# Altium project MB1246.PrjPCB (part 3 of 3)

## Sheet LCD Connectors.SchDoc: LCD Connectors
size A4; DocumentNumber: MB1246; Revision: B.2; SheetNumber: 6; SheetTotal: 17; Project: STM32H7x3I-EVAL
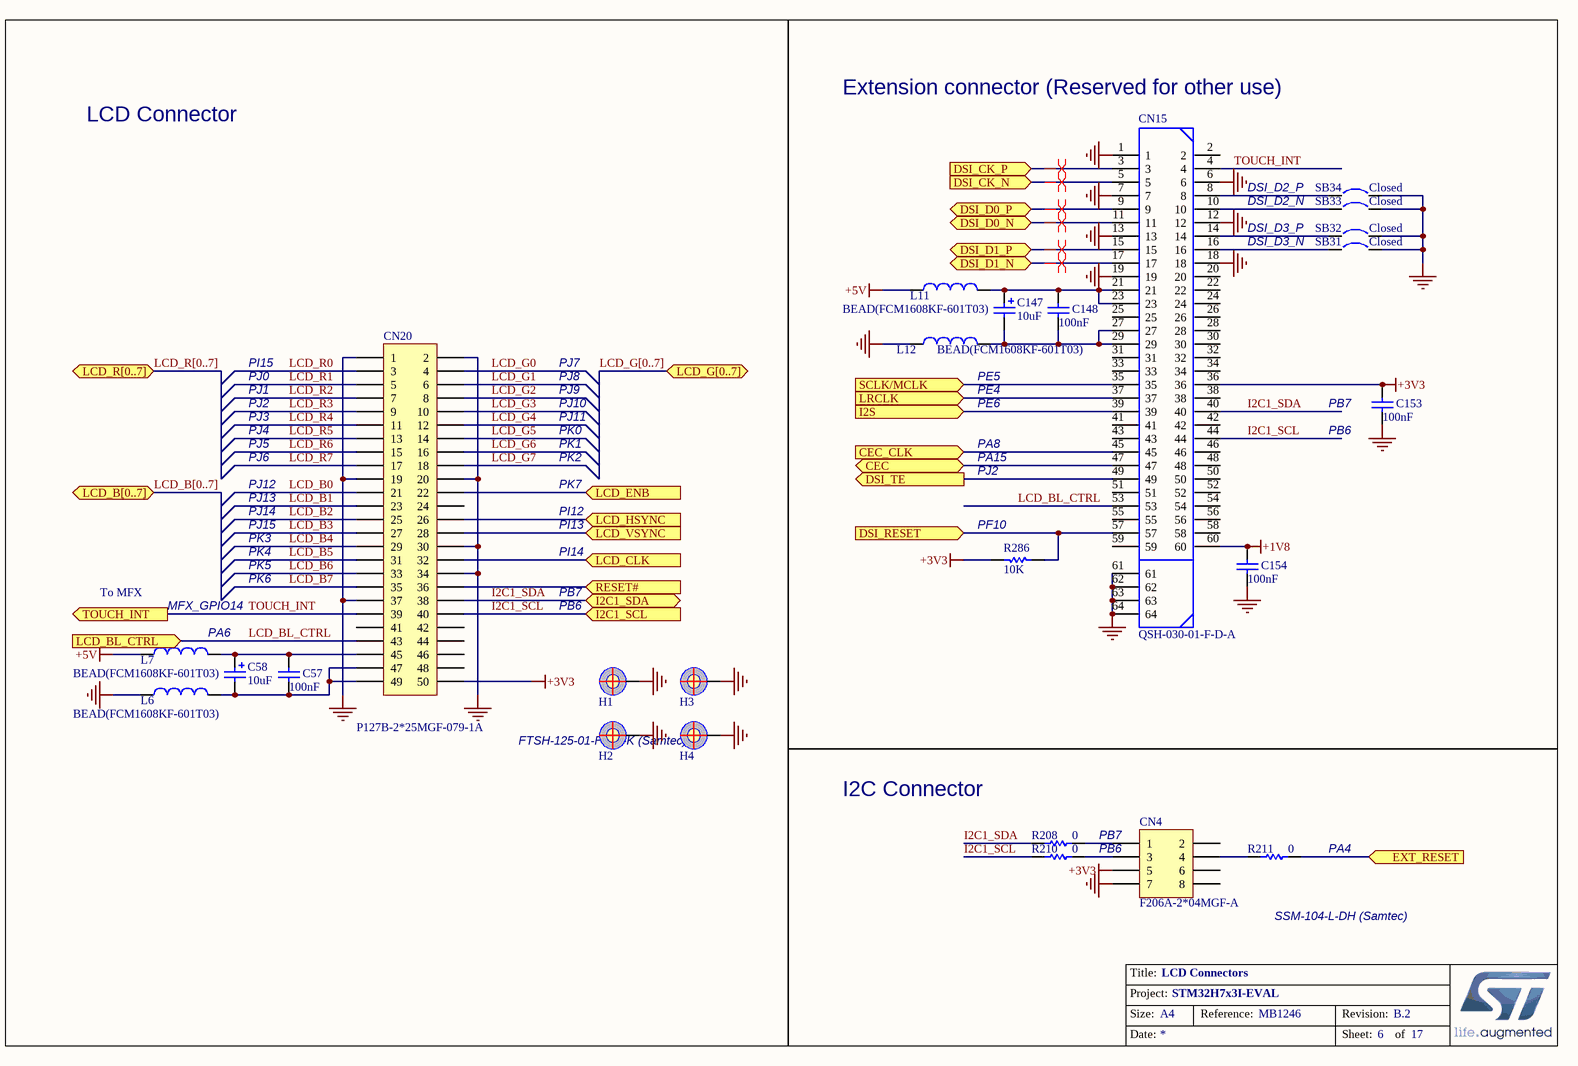
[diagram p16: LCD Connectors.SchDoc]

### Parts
C57  100nF  [0603C]
C58  10uF  [TAN-A]
C147  10uF  [TAN-A]
C148  100nF  [0603C]
C153  100nF  [0603C]
C154  100nF  [0603C]
CN4  F206A-2*04MGF-A  [SSM-104-L-DH]
CN15  QSH-030-01-F-D-A  [QSH-030-01-F-D-A]
CN20  P127B-2*25MGF-079-1A  [FTSH-125-01-F-DV]
H1  POSITION HOLE  [HOLE_C9D4R5]  (value not drawn)
H2  POSITION HOLE  [HOLE_C9D4R5]  (value not drawn)
H3  POSITION HOLE  [HOLE_C9D4R5]  (value not drawn)
H4  POSITION HOLE  [HOLE_C9D4R5]  (value not drawn)
L6  BEAD(FCM1608KF-601T03)  [0603L]
L7  BEAD(FCM1608KF-601T03)  [0603L]
L11  BEAD(FCM1608KF-601T03)  [0603L]
L12  BEAD(FCM1608KF-601T03)  [0603L]
R208  0  [0603R]
R210  0  [0603R]
R211  0  [0603R]
R286  10K  [0603R]
SB31  Closed  [SB_0603]
SB32  Closed  [SB_0603]
SB33  Closed  [SB_0603]
SB34  Closed  [SB_0603]

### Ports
CEC (bidir), CEC_CLK (in), DSI_CK_N (in), DSI_CK_P (in), DSI_D0_N (bidir), DSI_D0_P (bidir), DSI_D1_N (bidir), DSI_D1_P (bidir), DSI_RESET (in), DSI_TE (out), EXT_RESET (in), I2C1_SCL (in), I2C1_SDA (bidir), I2S (in), LCD_B[0..7] (bidir), LCD_BL_CTRL (in), LCD_CLK (in), LCD_ENB (in), LCD_G[0..7] (bidir), LCD_HSYNC (in), LCD_R[0..7] (bidir), LCD_VSYNC (in), LRCLK (in), RESET# (in), SCLK/MCLK (in), TOUCH_INT (out)

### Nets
+1V8: C154.1 CN15.60
+3V3: C153.1 CN4.5 CN15.36 CN20.50 R286.2
+5V: L7.1 L11.1
GND: C153.2 C154.2 CN4.7 CN15.1 CN15.6 CN15.7 CN15.12 CN15.13 CN15.18 CN15.19 CN15.61 CN15.62 CN15.63 CN15.64 CN20.1 CN20.2 CN20.19 CN20.20 CN20.30 CN20.34 CN20.37 H1.1 H2.1 H3.1 H4.1 L6.1 L12.1 SB31.2 SB32.2 SB33.2 SB34.2
I2C1_SCL: CN15.44 CN20.40 R210.1 ; port I2C1_SCL
I2C1_SDA: CN15.40 CN20.38 R208.1 ; port I2C1_SDA
LCD_B0: CN20.21
LCD_B1: CN20.23
LCD_B2: CN20.25
LCD_B3: CN20.27
LCD_B4: CN20.29
LCD_B5: CN20.31
LCD_B6: CN20.33
LCD_B7: CN20.35
LCD_BL_CTRL: CN15.53 CN20.43 ; port LCD_BL_CTRL
LCD_G0: CN20.4
LCD_G1: CN20.6
LCD_G2: CN20.8
LCD_G3: CN20.10
LCD_G4: CN20.12
LCD_G5: CN20.14
LCD_G6: CN20.16
LCD_G7: CN20.18
LCD_R0: CN20.3
LCD_R1: CN20.5
LCD_R2: CN20.7
LCD_R3: CN15.49 CN20.9 ; port DSI_TE
LCD_R4: CN20.11
LCD_R5: CN20.13
LCD_R6: CN20.15
LCD_R7: CN20.17
PA4: R211.2 ; port EXT_RESET
PA8: CN15.45 ; port CEC_CLK
PA15: CN15.47 ; port CEC
PF10: CN15.57 R286.1 ; port DSI_RESET
PI12: CN20.26 ; port LCD_HSYNC
PI13: CN20.28 ; port LCD_VSYNC
PI14: CN20.32 ; port LCD_CLK
PK7: CN20.22 ; port LCD_ENB
RESET#: CN20.36 ; port RESET#
TOUCH_INT: CN15.4 CN20.39 ; port TOUCH_INT
NetC57_1: C57.1 C58.1 CN20.45 L7.2
NetC57_2: C57.2 C58.2 CN20.47 CN20.49 L6.2
NetC147_1: C147.1 C148.1 CN15.21 CN15.23 L11.2
NetC147_2: C147.2 C148.2 CN15.27 CN15.29 L12.2
NetCN4_1: CN4.1 R208.2
NetCN4_3: CN4.3 R210.2
NetCN4_4: CN4.4 R211.1
NetCN15_3: CN15.3 ; port DSI_CK_P
NetCN15_5: CN15.5 ; port DSI_CK_N
NetCN15_8: CN15.8 SB34.1
NetCN15_9: CN15.9 ; port DSI_D0_P
NetCN15_10: CN15.10 SB33.1
NetCN15_11: CN15.11 ; port DSI_D0_N
NetCN15_14: CN15.14 SB32.1
NetCN15_15: CN15.15 ; port DSI_D1_P
NetCN15_16: CN15.16 SB31.1
NetCN15_17: CN15.17 ; port DSI_D1_N
NetCN15_35: CN15.35 ; port SCLK/MCLK
NetCN15_37: CN15.37 ; port LRCLK
NetCN15_39: CN15.39 ; port I2S

Not connected (* = marked no-connect by the designer): CN4 2 6 8; CN15 2 20 22 24 25 26 28 30 31 32 33 34 38 41 42 43 46 48 50 51 52 54 55 56 58 59; CN20 24 41 42 44 46 48

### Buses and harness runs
bus LCD_B[0..7] = port LCD_B[0..7]
bus LCD_G[0..7] = port LCD_G[0..7]
bus LCD_R[0..7] = port LCD_R[0..7]

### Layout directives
differential pair: NetCN15_3, NetCN15_5, NetCN15_9, NetCN15_11, NetCN15_15, NetCN15_17

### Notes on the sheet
- LCD Connector
- Extension connector (Reserved for other use)
- DSI_D2_P
- DSI_D2_N
- DSI_D3_P
- DSI_D3_N
- PI15
- PJ0
- PJ1
- PJ7
- PJ8
- PJ9
- (near L12) PE5
- (near L12) PE4
- PJ2
- PJ3
- PJ4
- PJ5
- PJ6
- PJ10
- PJ11
- PK0
- PK1
- PK2
- PE6
- PA15
- PA8
- (near C153) PB7
- (near C153) PB6
- PJ12
- PJ13
- PJ14
- PJ15
- PK7
- PI12
- PI13
- (near R286) PF10
- To MFX
- PK3
- PK4
- PK5
- PK6
- PI14
- PB7
- MFX_GPIO14
- (near L7) PA6
- PB6
- FTSH-125-01-F-DV-K (Samtec)
- I2C Connector
- (near R211) PA4
- (near CN4) SSM-104-L-DH (Samtec)

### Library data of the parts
C57 C148 C153 C154 = Cap: Capacitor; Value: 10nF
C58 C147 = Cap Pol1: Polarized Capacitor (Radial)
CN4 = SSM-104-L-DH: Header, 5-Pin, Dual row
CN15 = QSH-030-01-F-D-A: HIGH SPEED SOCKET STRIP, .5mm PITCH, 60 PINS; MANUFACTURER: SAMTEC; PCB DECAL: QSH-030-01-X-D-A
CN20 = Header 25X2: Header, 26-Pin, Dual row
L6 L7 L11 L12 = Inductor: Value: 100uH
R208 R210 R211 R286 = Res1: Resistor; Value: 1K
SB31-SB34 = Circuit Breaker_close: Circuit Breaker

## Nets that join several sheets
+1V8: Audio (6 pins), Power (SB36.2 SB37.2 TP12.1), USB_OTG (C141.1 R130.1 U13.28 U13.30), LCD Connectors (C154.1 CN15.60)
+2V9_SD: Power (5 pins), SD card (CN13.4 SB26.1)
+3V3: MB1246 (R209.1 R212.1), Audio (11 pins), ExtensionConnector (CN6.48 CN7.48 CN12.40), FDCAN&QSPI (9 pins), Memory (45 pins), MFX (13 pins), Power (9 pins), ST_LINK_V2-1 (R164.1), USB_OTG_FS (R144.1 R165.2 R290.2), SD card (7 pins), JTAG&Trace (8 pins), Ethernet (8 pins), RS232 (C104.1 U4.22 U4.26), Peripherals (15 pins), MCU (R247.1 SW1.1), USB_OTG (11 pins), LCD Connectors (5 pins)
+5V: ExtensionConnector (CN6.60 CN7.60), FDCAN&QSPI (C100.1 U2.3), Power (13 pins), ST_LINK_V2-1 (D16.1), USB_OTG_FS (U18.5), USB_OTG (C39.1 U13.21 U14.5), LCD Connectors (L7.1 L11.1)
D5V: ExtensionConnector (CN6.49 CN7.49), Power (JP10.7), ST_LINK_V2-1 (D7.1)
E5V: Power (C36.1 JP10.9 L3.3), ST_LINK_V2-1 (D8.1)
GND: Audio (43 pins), ExtensionConnector (20 pins), FDCAN&QSPI (14 pins), Memory (40 pins), MFX (16 pins), Power (106 pins), ST_LINK_V2-1 (42 pins), USB_OTG_FS (13 pins), SD card (5 pins), JTAG&Trace (24 pins), Ethernet (22 pins), RS232 (8 pins), Peripherals (16 pins), MCU (16 pins), USB_OTG (40 pins), LCD Connectors (31 pins)
U5V_ST_LINK: Power (JP10.11), ST_LINK_V2-1 (C49.2 SB35.2 U19.6 U19.7)
VBUS_FS1: Power (JP10.3), ST_LINK_V2-1 (D5.1), USB_OTG_FS (5 pins), MCU (R255.1)
VBUS_FS2: Power (JP10.5), ST_LINK_V2-1 (D6.1), MCU (R254.1), USB_OTG (CN16.1 D13.6 R135.1 SB28.1)
VBUS_HS: Power (JP10.1), ST_LINK_V2-1 (D4.1), USB_OTG (CN14.1 D11.A1 L5.2)
A0: ExtensionConnector (CN12.14), Memory (U12.E2 U15.G8 U16.A3), MCU (R224.1)
A1: ExtensionConnector (CN12.12), Memory (U12.D2 U15.G9 U16.A4), MCU (R226.1)
A2: ExtensionConnector (CN12.8), Memory (U12.C2 U15.F7 U16.A5), MCU (R222.1)
A3: ExtensionConnector (CN12.5), Memory (U12.A2 U15.F3 U16.B3), MCU (R223.1)
A4: ExtensionConnector (CN12.3), Memory (U12.B2 U15.G1 U16.B4), MCU (R221.1)
A5: ExtensionConnector (CN12.1), Memory (U12.D3 U15.G2 U16.C3), MCU (R219.1)
A6: ExtensionConnector (CN11.5), Memory (U12.C3 U15.G3 U16.C4), MCU (R250.1)
A7: ExtensionConnector (CN11.3), Memory (U12.A3 U15.H1 U16.D4), MCU (R251.1)
A8: ExtensionConnector (CN11.4), Memory (U12.B6 U15.H2 U16.H2), MCU (R53.1)
A9: ExtensionConnector (CN11.18), Memory (U12.A6 U15.J3 U16.H3), MCU (R279.1)
A10: ExtensionConnector (CN11.6), Memory (U12.C6 U15.G7 U16.H4), MCU (R50.1)
A11: ExtensionConnector (CN11.7), Memory (U12.D6 U15.H9 U16.H5), MCU (R51.1)
A12: ExtensionConnector (CN11.33), Memory (U12.B7 U16.G3), MCU (R270.1)
A13: ExtensionConnector (CN11.34), Memory (U12.A7 U16.G4), MCU (R260.1)
A14: ExtensionConnector (CN11.28), Memory (U12.C7 U15.J7 U16.F3), MCU (R261.1)
A15: ExtensionConnector (CN11.25), Memory (U12.D7 U15.H8 U16.F4), MCU (R272.1)
A16: ExtensionConnector (CN11.21), Memory (U12.E7 U16.E4), MCU (R275.2)
A17: ExtensionConnector (CN11.23), Memory (U12.B3 U16.D3), MCU (R274.1)
A18: ExtensionConnector (CN11.31), Memory (U12.C4 U16.H1), MCU (R271.1)
A19: ExtensionConnector (CN12.13), Memory (U12.D5 U16.G2), MCU (R236.1 R238.1)
A20: ExtensionConnector (CN12.11), Memory (U12.D4 U16.H6), MCU (R231.1 R233.1)
A21: ExtensionConnector (CN12.4), Memory (U12.C5), MCU (R217.1 R218.1)
A22: ExtensionConnector (CN12.7), Memory (U12.B8), MCU (R227.1 R230.1)
A23: ExtensionConnector (CN12.16), Memory (U12.C8), MCU (R234.1 R241.1)
BK2_IO0: ExtensionConnector (CN6.17), FDCAN&QSPI (R52.1 R253.1), MCU (R228.2)
BK2_IO1: ExtensionConnector (CN6.15), FDCAN&QSPI (R28.2 R229.2), MCU (R235.2)
BK2_IO2: ExtensionConnector (CN6.32), FDCAN&QSPI (R33.1 R237.1), MCU (R244.2)
BK2_IO3: ExtensionConnector (CN6.13), FDCAN&QSPI (R27.2 R225.2), MCU (R29.2)
D0: ExtensionConnector (CN11.39), Memory (U12.E3 U15.R8 U16.B6), MCU (R77.1)
D1: ExtensionConnector (CN11.38), Memory (U12.H3 U15.N7 U16.C5), MCU (R269.1)
D2: ExtensionConnector (CN12.31), Memory (U12.E4 U15.R9 U16.C6), MCU (R265.1)
D3: ExtensionConnector (CN12.32), Memory (U12.H4 U15.N8 U16.D5), MCU (R262.1)
D4: ExtensionConnector (CN11.11), Memory (U12.H5 U15.P9 U16.E5), MCU (R54.1)
D5: ExtensionConnector (CN11.14), Memory (U12.E5 U15.M8 U16.F5), MCU (R67.1)
D6: ExtensionConnector (CN11.12), Memory (U12.H6 U15.M7 U16.F6), MCU (R66.1)
D7: ExtensionConnector (CN11.13), Memory (U12.E6 U15.L8 U16.G6), MCU (R280.1)
D8: ExtensionConnector (CN11.16), Memory (U12.F3 U15.L2 U16.B1), MCU (R68.1)
D9: ExtensionConnector (CN11.15), Memory (U12.G3 U15.M3 U16.C1), MCU (R278.1)
D10: ExtensionConnector (CN11.19), Memory (U12.F4 U15.M2 U16.C2), MCU (R70.1)
D11: ExtensionConnector (CN11.20), Memory (U12.G4 U15.P1 U16.D2), MCU (R277.1)
D12: ExtensionConnector (CN11.17), Memory (U12.F5 U15.N2 U16.E2), MCU (R69.1)
D13: ExtensionConnector (CN11.35), Memory (U12.G6 U15.R1 U16.F2), MCU (R73.1)
D14: ExtensionConnector (CN11.37), Memory (U12.F6 U15.N3 U16.F1), MCU (R76.1)
D15: ExtensionConnector (CN11.36), Memory (U12.G7 U15.R2 U16.G1), MCU (R75.1)
D16: ExtensionConnector (CN11.22), Memory (U15.E8), MCU (R71.2)
D17: ExtensionConnector (CN11.26), Memory (U15.D7), MCU (R72.2)
D18: ExtensionConnector (CN11.24), Memory (U15.D8), MCU (R276.2)
D19: ExtensionConnector (CN11.27), Memory (U15.B9), MCU (R273.2)
D20: ExtensionConnector (CN11.32), Memory (U15.C8), MCU (R74.2)
D21: ExtensionConnector (CN12.39), Memory (U15.A9), MCU (R258.2)
D22: ExtensionConnector (CN12.38), Memory (U15.C7), MCU (R257.2)
D23: ExtensionConnector (CN12.36), Memory (U15.A8), MCU (R266.2)
D24: ExtensionConnector (CN12.37), Memory (U15.A2), MCU (R256.1)
D25: ExtensionConnector (CN12.35), Memory (U15.C3), MCU (R264.1)
D26: ExtensionConnector (CN12.33), Memory (U15.A1), MCU (R263.1)
D27: ExtensionConnector (CN12.34), Memory (U15.C2), MCU (R267.1)
D28: ExtensionConnector (CN12.22), Memory (U15.B1), MCU (R243.1)
D29: ExtensionConnector (CN12.18), Memory (U15.D2), MCU (R240.1)
D30: ExtensionConnector (CN12.20), Memory (U15.D3), MCU (R242.1)
D31: ExtensionConnector (CN12.21), Memory (U15.E2), MCU (R246.1)
I2C1_SCL: MB1246 (R212.2), Audio (R155.1), ExtensionConnector (CN7.18), MFX (R180.1), MCU (U7.B5), LCD Connectors (CN15.44 CN20.40 R210.1)
I2C1_SDA: MB1246 (R209.2), Audio (R160.1), ExtensionConnector (CN7.16), MFX (R181.1), MCU (U7.C5), LCD Connectors (CN15.40 CN20.38 R208.1)
LCD_B0: ExtensionConnector (CN7.32), JTAG&Trace (SB25.2), MCU (U7.D11), LCD Connectors (CN20.21)
LCD_B1: ExtensionConnector (CN7.24), MCU (U7.E10), LCD Connectors (CN20.23)
LCD_B2: ExtensionConnector (CN7.28), MCU (U7.D10), LCD Connectors (CN20.25)
LCD_B3: ExtensionConnector (CN7.29), MCU (U7.B10), LCD Connectors (CN20.27)
LCD_B4: ExtensionConnector (CN7.23), Peripherals (R202.1), MCU (U7.C8), LCD Connectors (CN20.29)
LCD_B5: ExtensionConnector (CN7.21), Peripherals (R201.1), MCU (U7.B8), LCD Connectors (CN20.31)
LCD_B6: ExtensionConnector (CN7.22), Peripherals (R200.1), MCU (U7.A8), LCD Connectors (CN20.33)
LCD_B7: ExtensionConnector (CN7.17), Peripherals (R199.1), MCU (U7.C7), LCD Connectors (CN20.35)
LCD_BL_CTRL: ExtensionConnector (CN6.25), MCU (U7.R3), LCD Connectors (CN15.53 CN20.43)
LCD_G0: ExtensionConnector (CN6.53), JTAG&Trace (SB24.2), MCU (U7.N14), LCD Connectors (CN20.4)
LCD_G1: ExtensionConnector (CN6.54), MCU (U7.N13), LCD Connectors (CN20.6)
LCD_G2: ExtensionConnector (CN6.56), MCU (U7.M14), LCD Connectors (CN20.8)
LCD_G3: ExtensionConnector (CN6.58), MCU (U7.L14), LCD Connectors (CN20.10)
LCD_G4: ExtensionConnector (CN7.31), MCU (U7.K14), LCD Connectors (CN20.12)
LCD_G5: ExtensionConnector (CN7.55), MCU (U7.J14), LCD Connectors (CN20.14)
LCD_G6: ExtensionConnector (CN7.57), MCU (U7.J15), LCD Connectors (CN20.16)
LCD_G7: ExtensionConnector (CN7.58), MCU (U7.H17), LCD Connectors (CN20.18)
LCD_R0: ExtensionConnector (CN6.38), MCU (U7.P5), LCD Connectors (CN20.3)
LCD_R1: ExtensionConnector (CN6.43), MCU (U7.N6), LCD Connectors (CN20.5)
LCD_R2: ExtensionConnector (CN6.41), MCU (U7.P6), LCD Connectors (CN20.7)
LCD_R3: ExtensionConnector (CN6.40), MCU (U7.T6), LCD Connectors (CN15.49 CN20.9)
LCD_R4: ExtensionConnector (CN6.33), MCU (U7.U6), LCD Connectors (CN20.11)
LCD_R5: ExtensionConnector (CN6.36), MCU (U7.U7), LCD Connectors (CN20.13)
LCD_R6: ExtensionConnector (CN6.42), MCU (U7.R12), LCD Connectors (CN20.15)
LCD_R7: ExtensionConnector (CN6.55), MCU (U7.N15), LCD Connectors (CN20.17)
NCS2: FDCAN&QSPI (R20.1 SB6.2 U6.6 U28.7), MCU (SB45.1)
NetB4_1: MFX (U24.20), Peripherals (B4.1 C88.2 R189.2)
NetB4_2: MFX (U24.18), Peripherals (B4.2 C87.2 R188.2)
NetB4_3: MFX (U24.19), Peripherals (B4.3 C86.2 R187.2)
NetB4_4: MFX (U24.39), Peripherals (B4.4 C90.2 R191.2)
NetB4_6: MFX (U24.40), Peripherals (B4.6 C89.2 R190.2)
NetCN8_12: JTAG&Trace (CN8.12 U8.1), MCU (SB15.1)
NetCN8_14: JTAG&Trace (CN8.14 R63.1 U10.5), MCU (SB9.1)
NetCN8_16: JTAG&Trace (CN8.16 R78.1 U10.4), MCU (SB7.1)
NetCN8_18: JTAG&Trace (CN8.18 U10.3), MCU (SB41.1)
NetCN8_20: JTAG&Trace (CN8.20 U10.1), MCU (SB3.1)
NetCN13_10: MFX (U24.28), SD card (CN13.10 M1.9)
NetCN15_3: MCU (U7.L16), LCD Connectors (CN15.3)
NetCN15_5: MCU (U7.L17), LCD Connectors (CN15.5)
NetCN15_9: MCU (U7.M16), LCD Connectors (CN15.9)
NetCN15_11: MCU (U7.M17), LCD Connectors (CN15.11)
NetCN15_15: MCU (U7.K16), LCD Connectors (CN15.15)
NetCN15_17: MCU (U7.K17), LCD Connectors (CN15.17)
NetCN15_35: Audio (U22.G1), MCU (SB42.1), LCD Connectors (CN15.35)
NetCN15_37: Audio (U22.E3), MCU (SB5.1), LCD Connectors (CN15.37)
NetCN15_39: Audio (U22.E4), MCU (SB2.1), LCD Connectors (CN15.39)
NetCN16_2: MCU (SB47.1), USB_OTG (CN16.2 D13.4)
NetCN16_3: MCU (SB49.1), USB_OTG (CN16.3 D13.3)
NetCN16_4: MCU (SB48.1), USB_OTG (CN16.4 D13.1)
NetCN18_2: USB_OTG_FS (CN18.2 D14.4), MCU (SB59.1)
NetCN18_3: USB_OTG_FS (CN18.3 D14.3), MCU (SB60.1)
NetD3_1: RS232 (U4.20), MCU (D3.1)
NetJP2_2: FDCAN&QSPI (U2.1), MCU (JP2.2)
NetJP6_2: RS232 (U4.16), MCU (JP6.2)
NetJP7_1: MB1246 (JP7.1), RS232 (U4.13)
NetJP7_2: MB1246 (JP7.2), MCU (SB46.1)
NetJP8_1: MB1246 (JP8.1), RS232 (U4.17)
NetJP8_2: MB1246 (JP8.2), MCU (SB51.1)
NetM1_1: MFX (U24.26), SD card (M1.1 R84.2)
NetM1_23: SD card (M1.23 R93.1), MCU (SB58.2)
NetR12_2: Peripherals (R12.2), MCU (SB43.2)
NetR126_1: MFX (U24.29), USB_OTG (R126.1)
NetR141_2: MFX (U24.17), USB_OTG_FS (R141.2)
NetR146_1: MFX (U24.16), USB_OTG_FS (R146.1)
NetR295_1: MFX (U24.31), Peripherals (R295.1)
NetR297_1: MFX (U24.32), Peripherals (R297.1)
NetSB8_1: Audio (U22.F2), MCU (SB8.1)
NetSB11_1: Audio (SW2.4), MCU (SB11.1)
NetSB29_1: MFX (U24.30), USB_OTG (SB29.1)
NetSB38_1: Ethernet (U5.13), MCU (SB38.1)
NetSB50_1: FDCAN&QSPI (U2.4), MCU (SB50.1)
NetSB61_1: MFX (U24.33), USB_OTG (SB61.1)
NetU22_G3: Audio (U22.G3), MFX (U24.15)
PA0: ExtensionConnector (CN7.27), MFX (R173.2), Peripherals (R203.2), MCU (U7.N5)
PA0_C: ExtensionConnector (CN6.16), MCU (SB43.1 U7.T1)
PA1: ExtensionConnector (CN6.35), Ethernet (R31.2), MCU (U7.N4)
PA1_C: ExtensionConnector (CN6.18), MCU (U7.T2)
PA2: ExtensionConnector (CN7.8), Ethernet (R47.2), MCU (U7.N3)
PA3: ExtensionConnector (CN6.21), MCU (U7.U2), USB_OTG (R114.2)
PA4: ExtensionConnector (CN6.19), Peripherals (R296.1), MCU (U7.U3), LCD Connectors (R211.2)
PA5: ExtensionConnector (CN6.22), MCU (U7.T3), USB_OTG (R118.2)
PA7: ExtensionConnector (CN6.34), Ethernet (R44.2), MCU (U7.R5)
PA8: ExtensionConnector (CN7.52), Ethernet (JP5.3), MCU (U7.E15), LCD Connectors (CN15.45)
PA9: ExtensionConnector (CN7.46), MCU (R255.2 U7.D15)
PA10: ExtensionConnector (CN7.47), USB_OTG_FS (CN18.4 D14.1), MCU (U7.D14)
PA11: ExtensionConnector (CN7.54), MCU (SB50.2 SB59.2 U7.E17)
PA12: ExtensionConnector (CN7.56), MCU (JP2.1 SB60.2 U7.E16)
PA13: ExtensionConnector (CN7.43), ST_LINK_V2-1 (U23.25 U23.27), JTAG&Trace (R55.2), MCU (U7.C15)
PA14: ExtensionConnector (CN7.38), ST_LINK_V2-1 (U23.15 U23.26), JTAG&Trace (R59.2), MCU (U7.B14)
PA15: ExtensionConnector (CN7.35), ST_LINK_V2-1 (U23.17), JTAG&Trace (R61.2), MCU (U7.A14), LCD Connectors (CN15.47)
PB0: ExtensionConnector (CN6.29), MCU (U7.U5), USB_OTG (R113.2)
PB1: ExtensionConnector (CN6.31), MCU (U7.T5), USB_OTG (R111.2)
PB2: ExtensionConnector (CN6.24), FDCAN&QSPI (SB12.2 SB44.2 U6.16), MCU (R34.2)
PB3: ExtensionConnector (CN7.15), ST_LINK_V2-1 (U23.16 U23.31), JTAG&Trace (R60.2), MCU (U7.C6)
PB4: ExtensionConnector (CN7.20), ST_LINK_V2-1 (U23.19), JTAG&Trace (R79.2), MCU (U7.B7)
PB5: ExtensionConnector (CN6.9), MCU (U7.A5), USB_OTG (R101.2)
PB8: ExtensionConnector (CN7.11), SD card (M1.10), MCU (U7.D5)
PB9: ExtensionConnector (CN7.14), SD card (M1.24 R91.1), MCU (U7.D4)
PB10: ExtensionConnector (CN6.52), MCU (U7.P11), USB_OTG (R109.2)
PB11: ExtensionConnector (CN6.51), MCU (U7.P12), USB_OTG (R108.2)
PB12: ExtensionConnector (CN6.46), MCU (SB48.2 U7.T14), USB_OTG (R105.2)
PB13: ExtensionConnector (CN6.44), MCU (R254.2 U7.U14), USB_OTG (R104.2)
PB14: ExtensionConnector (CN6.45), MCU (SB46.2 SB47.2 U7.U15)
PB15: ExtensionConnector (CN6.47), MCU (SB49.2 SB51.2 U7.T15)
PC0: ExtensionConnector (CN6.1), MCU (U7.L2), USB_OTG (R124.2)
PC1: Audio (SW2.8), ExtensionConnector (CN6.2), MCU (SB38.2 U7.M2)
PC2: Audio (SW2.2), ExtensionConnector (CN7.2), MCU (U7.M3)
PC2_C: ExtensionConnector (CN6.12), MCU (U7.R1)
PC3: Audio (SW2.6), ExtensionConnector (CN6.37), MCU (U7.M4)
PC3_C: ExtensionConnector (CN6.14), MCU (U7.R2)
PC4: ExtensionConnector (CN6.27), Ethernet (R41.2), MCU (U7.T4)
PC5: ExtensionConnector (CN6.28), Ethernet (R39.2), MCU (U7.U4)
PC6: ExtensionConnector (CN7.45), MCU (SB58.1 U7.F14)
PC7: ExtensionConnector (CN7.42), SD card (M1.11 R92.1), MCU (U7.F13)
PC8: ExtensionConnector (CN7.44), SD card (M1.6), MCU (U7.E13)
PC9: ExtensionConnector (CN7.53), SD card (M1.8), MCU (U7.E14)
PC10: ExtensionConnector (CN7.36), SD card (M1.2), MCU (U7.A13)
PC11: ExtensionConnector (CN7.40), SD card (M1.3), MCU (SB45.2 U7.B13)
PC12: ExtensionConnector (CN7.33), SD card (M1.4 R83.1), MCU (U7.C12)
PC13: ExtensionConnector (CN7.9), Peripherals (R193.2), MCU (U7.E3)
PC14: ExtensionConnector (SB1.1), MCU (R18.1 U7.C2)
PC15: ExtensionConnector (SB4.1), MCU (R17.1 U7.C1)
PD2: ExtensionConnector (CN7.41), SD card (M1.7), MCU (U7.D12)
PD3: ExtensionConnector (CN7.34), FDCAN&QSPI (R4.1 U2.8), MCU (U7.B12)
PD4: ExtensionConnector (CN12.28), Memory (U12.G2 U16.A2), MCU (U7.A12)
PD5: ExtensionConnector (CN12.26), Memory (R95.2), MCU (U7.A11)
PD6: ExtensionConnector (CN12.6), Memory (R89.1 U12.A4), MCU (U7.B11)
PD7: ExtensionConnector (CN12.24), Memory (R88.2), MCU (U7.C11)
PE0: ExtensionConnector (CN12.25), Memory (U15.K9 U16.A1), MCU (U7.C4)
PE1: ExtensionConnector (CN12.23), Memory (U15.K1 U16.B2), MCU (U7.B4)
PF6: ExtensionConnector (CN6.8), FDCAN&QSPI (R26.2), MCU (R14.1)
PF7: ExtensionConnector (CN6.4), FDCAN&QSPI (R36.1), MCU (R13.1)
PF8: ExtensionConnector (CN6.11), FDCAN&QSPI (R38.1), MCU (R232.1)
PF9: ExtensionConnector (CN6.23), FDCAN&QSPI (R32.2), MCU (R239.1)
PF10: ExtensionConnector (CN7.1), Peripherals (R294.1), MCU (U7.L3), LCD Connectors (CN15.57 R286.1)
PF11: ExtensionConnector (CN11.8), Memory (U15.J9), MCU (R252.1)
PG6: ExtensionConnector (CN6.57), FDCAN&QSPI (R19.1 SB6.1 U6.7), MCU (R259.2)
PG7: ExtensionConnector (CN7.51), MCU (SB56.2 U7.F16)
PG8: ExtensionConnector (CN11.40), Memory (U15.J1), MCU (R268.1)
PG10: ExtensionConnector (CN12.27), Memory (R128.2), MCU (U7.A9)
PG11: ExtensionConnector (CN7.37), Ethernet (U5.16), MCU (R49.1)
PG12: ExtensionConnector (CN7.26), Ethernet (U5.18), MCU (R48.1)
PG13: ExtensionConnector (CN7.25), Ethernet (U5.17), MCU (R37.1)
PG15: ExtensionConnector (CN12.19), Memory (U15.K7), MCU (R245.1)
PH0: ExtensionConnector (SB39.1), MCU (R15.2 U7.J2)
PH1: ExtensionConnector (SB40.1), MCU (R16.2 U7.J1)
PH4: ExtensionConnector (CN6.26), MCU (U7.P3), USB_OTG (R117.2)
PH5: ExtensionConnector (CN11.2), Memory (U15.K8), MCU (R248.2)
PH6: ExtensionConnector (CN11.1), Memory (U15.J8), MCU (R58.2)
PH7: ExtensionConnector (CN12.2), Memory (R282.2), MCU (U7.U13)
PI4: ExtensionConnector (CN12.17), Memory (U15.F8), MCU (U7.A4)
PI5: ExtensionConnector (CN12.15), Memory (U15.F2), MCU (U7.A3)
PI8: ExtensionConnector (CN7.12), MFX (R185.1), MCU (U7.E4)
PI11: ExtensionConnector (CN6.7), MCU (U7.F4), USB_OTG (R123.2)
PI12: ExtensionConnector (CN7.6), MCU (U7.H1), LCD Connectors (CN20.26)
PI13: ExtensionConnector (CN7.7), MCU (U7.H2), LCD Connectors (CN20.28)
PI14: ExtensionConnector (CN7.5), MCU (R220.1), LCD Connectors (CN20.32)
PK7: ExtensionConnector (CN7.13), MCU (U7.D7), LCD Connectors (CN20.22)
RESET#: ExtensionConnector (R215.1), MFX (D15.2), ST_LINK_V2-1 (U23.18), JTAG&Trace (R62.2), Ethernet (U5.15), MCU (5 pins), USB_OTG (SB52.1), LCD Connectors (CN20.36)
SAI1_MCLKA: Audio (U22.D3), MCU (SB56.1 SB57.1)
STLINK_RX: MB1246 (JP7.3), ST_LINK_V2-1 (CN24.1 U23.13)
STLINK_TX: MB1246 (JP8.3), ST_LINK_V2-1 (CN24.2 U23.12)
TOUCH_INT: MFX (U24.27), LCD Connectors (CN15.4 CN20.39)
